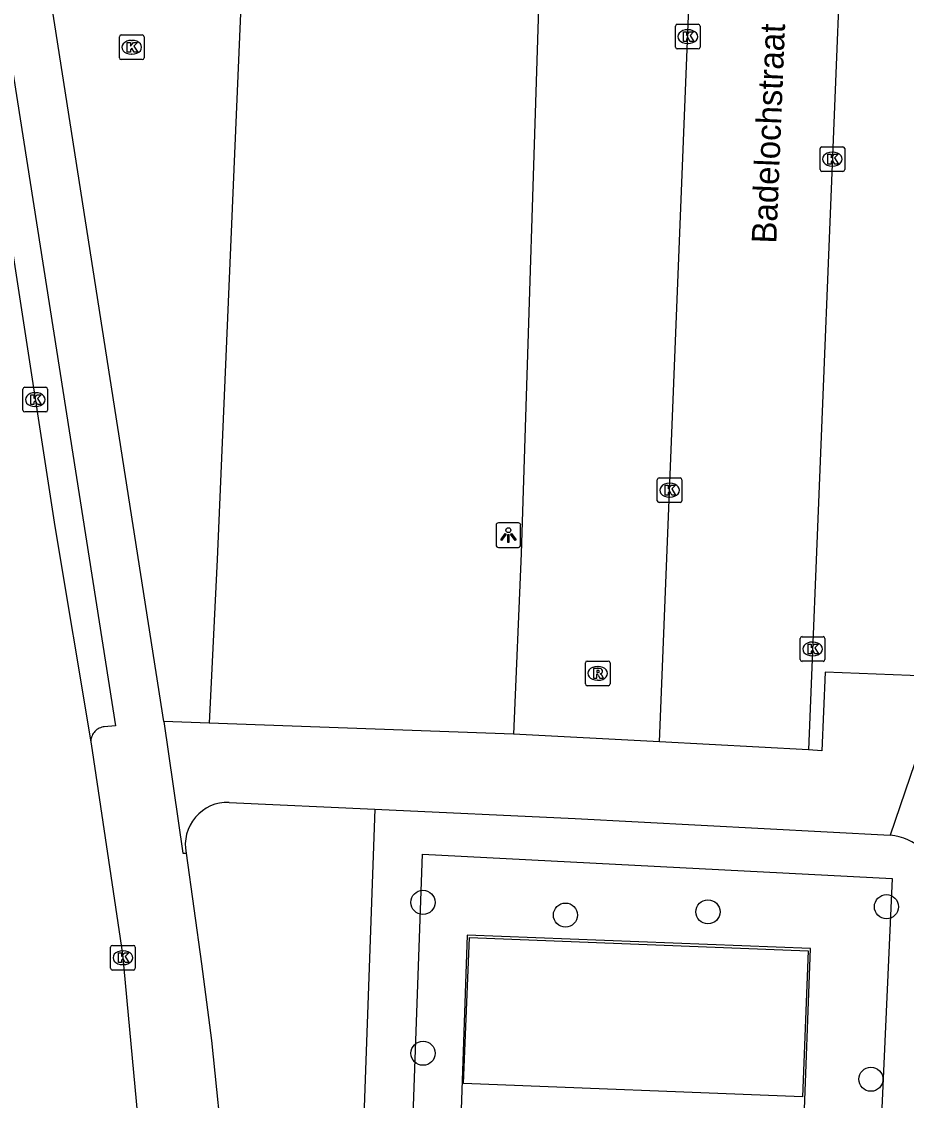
# Model space of a CAD drawing. Extents: x 160077 to 160945, y 386481 to 387498.
# Drawn here: x 160812.49 to 160848.36, y 386677.21 to 386720.98 of the extents above; entities that cross this region are included whole.
import ezdxf

# ---------------------------------------------------------------- set-up
doc = ezdxf.new("R2010")
doc.units = 0
for name, color, linetype in [('IMGEO_Boom', 7, 'Continuous'), ('IMGEO_Groenvoorziening', 7, 'Continuous'), ('IMGEO_Kolk', 7, 'Continuous'), ('IMGEO_Lichtpunt', 7, 'Continuous'), ('IMGEO_Openbare_ruimte_label', 7, 'Continuous'), ('IMGEO_Pand', 7, 'Continuous'), ('IMGEO_Parkeervlak_open', 7, 'Continuous'), ('IMGEO_Rijbaan_lokaal_open', 7, 'Continuous'), ('IMGEO_Rioolput', 7, 'Continuous'), ('IMGEO_Voetpad_open', 7, 'Continuous')]:
    doc.layers.add(name, color=color, linetype=linetype)

msp = doc.modelspace()

# ---------------------------------------------------------------- linework, layer by layer
at = {"layer": 'IMGEO_Boom'}
for centre in [(160828.763, 386685.248), (160840.318, 386684.863), (160847.555, 386685.072), (160834.541, 386684.732), (160828.767, 386679.126), (160846.925, 386678.073)]:
    msp.add_circle(centre, 0.489, dxfattribs=at)
at = {"layer": 'IMGEO_Groenvoorziening'}
for points in [[(160826.808, 386689.026), (160825.569, 386654.256)], [(160840.258, 386655.759), (160827.638, 386656.167), (160828.744, 386687.197), (160847.783, 386686.219), (160846.392, 386655.259), (160843.424, 386655.397)]]:
    msp.add_lwpolyline(points, dxfattribs=at)
at = {"layer": 'IMGEO_Kolk'}
for p, q in [((160839, 386719.942), (160839, 386720.794)), ((160839.075, 386720.868), (160839.927, 386720.868)), ((160840.001, 386720.794), (160840.001, 386719.942)), ((160816.455, 386719.51), (160816.455, 386720.362)), ((160816.53, 386720.436), (160817.382, 386720.436)), ((160817.456, 386720.362), (160817.456, 386719.51)), ((160839.488, 386720.648), (160839.513, 386720.648)), ((160816.943, 386720.216), (160816.968, 386720.216)), ((160839.927, 386719.868), (160839.075, 386719.868)), ((160839.511, 386720.088), (160839.486, 386720.088)), ((160817.382, 386719.436), (160816.53, 386719.436)), ((160816.966, 386719.656), (160816.941, 386719.656)), ((160844.938, 386715.898), (160845.79, 386715.898)), ((160844.863, 386714.972), (160844.863, 386715.824)), ((160845.351, 386715.678), (160845.376, 386715.678)), ((160845.864, 386715.824), (160845.864, 386714.972)), ((160845.374, 386715.118), (160845.349, 386715.118)), ((160845.79, 386714.898), (160844.938, 386714.898)), ((160812.544, 386705.217), (160812.544, 386706.069)), ((160812.619, 386706.143), (160813.471, 386706.143)), ((160813.032, 386705.923), (160813.057, 386705.923)), ((160813.545, 386706.069), (160813.545, 386705.217)), ((160813.471, 386705.143), (160812.619, 386705.143)), ((160813.055, 386705.363), (160813.03, 386705.363)), ((160838.262, 386701.542), (160838.262, 386702.394)), ((160838.337, 386702.468), (160839.189, 386702.468)), ((160839.263, 386702.394), (160839.263, 386701.542)), ((160838.75, 386702.248), (160838.775, 386702.248)), ((160839.189, 386701.468), (160838.337, 386701.468)), ((160838.773, 386701.688), (160838.748, 386701.688)), ((160844.061, 386695.1), (160844.061, 386695.952)), ((160844.136, 386696.026), (160844.988, 386696.026)), ((160844.549, 386695.806), (160844.574, 386695.806)), ((160845.062, 386695.952), (160845.062, 386695.1)), ((160844.988, 386695.026), (160844.136, 386695.026)), ((160844.572, 386695.246), (160844.547, 386695.246)), ((160816.172, 386683.502), (160817.024, 386683.502)), ((160816.097, 386682.576), (160816.097, 386683.428)), ((160816.585, 386683.282), (160816.61, 386683.282)), ((160817.098, 386683.428), (160817.098, 386682.576)), ((160816.608, 386682.722), (160816.583, 386682.722)), ((160817.024, 386682.502), (160816.172, 386682.502))]:
    msp.add_line(p, q, dxfattribs=at)
for points in [[(160839, 386719.942), (160839, 386720.794)], [(160839.075, 386720.868), (160839.927, 386720.868)], [(160840.001, 386720.794), (160840.001, 386719.942)], [(160816.455, 386719.51), (160816.455, 386720.362)], [(160816.53, 386720.436), (160817.382, 386720.436)], [(160817.456, 386720.362), (160817.456, 386719.51)], [(160839.321, 386720.568), (160839.444, 386720.568), (160839.444, 386720.417), (160839.574, 386720.568), (160839.738, 386720.568), (160839.592, 386720.417), (160839.745, 386720.168), (160839.593, 386720.168), (160839.508, 386720.332), (160839.444, 386720.265), (160839.444, 386720.168), (160839.321, 386720.168), (160839.321, 386720.568)], [(160816.776, 386720.136), (160816.899, 386720.136), (160816.899, 386719.985), (160817.029, 386720.136), (160817.193, 386720.136), (160817.047, 386719.985), (160817.2, 386719.736), (160817.048, 386719.736), (160816.963, 386719.9), (160816.899, 386719.833), (160816.899, 386719.736), (160816.776, 386719.736), (160816.776, 386720.136)], [(160839.927, 386719.868), (160839.075, 386719.868)], [(160817.382, 386719.436), (160816.53, 386719.436)], [(160844.938, 386715.898), (160845.79, 386715.898)], [(160844.863, 386714.972), (160844.863, 386715.824)], [(160845.184, 386715.598), (160845.307, 386715.598), (160845.307, 386715.447), (160845.437, 386715.598), (160845.601, 386715.598), (160845.455, 386715.447), (160845.608, 386715.198), (160845.456, 386715.198), (160845.371, 386715.362), (160845.307, 386715.295), (160845.307, 386715.198), (160845.184, 386715.198), (160845.184, 386715.598)], [(160845.864, 386715.824), (160845.864, 386714.972)], [(160845.79, 386714.898), (160844.938, 386714.898)], [(160812.544, 386705.217), (160812.544, 386706.069)], [(160812.619, 386706.143), (160813.471, 386706.143)], [(160812.865, 386705.843), (160812.988, 386705.843), (160812.988, 386705.692), (160813.118, 386705.843), (160813.282, 386705.843), (160813.136, 386705.692), (160813.289, 386705.443), (160813.137, 386705.443), (160813.052, 386705.607), (160812.988, 386705.54), (160812.988, 386705.443), (160812.865, 386705.443), (160812.865, 386705.843)], [(160813.545, 386706.069), (160813.545, 386705.217)], [(160813.471, 386705.143), (160812.619, 386705.143)], [(160838.262, 386701.542), (160838.262, 386702.394)], [(160838.337, 386702.468), (160839.189, 386702.468)], [(160839.263, 386702.394), (160839.263, 386701.542)], [(160838.583, 386702.168), (160838.706, 386702.168), (160838.706, 386702.017), (160838.836, 386702.168), (160839, 386702.168), (160838.854, 386702.017), (160839.007, 386701.768), (160838.855, 386701.768), (160838.77, 386701.932), (160838.706, 386701.865), (160838.706, 386701.768), (160838.583, 386701.768), (160838.583, 386702.168)], [(160839.189, 386701.468), (160838.337, 386701.468)], [(160844.061, 386695.1), (160844.061, 386695.952)], [(160844.136, 386696.026), (160844.988, 386696.026)], [(160845.062, 386695.952), (160845.062, 386695.1)], [(160844.382, 386695.726), (160844.505, 386695.726), (160844.505, 386695.575), (160844.635, 386695.726), (160844.799, 386695.726), (160844.653, 386695.575), (160844.806, 386695.326), (160844.654, 386695.326), (160844.569, 386695.49), (160844.505, 386695.423), (160844.505, 386695.326), (160844.382, 386695.326), (160844.382, 386695.726)], [(160844.988, 386695.026), (160844.136, 386695.026)], [(160816.172, 386683.502), (160817.024, 386683.502)], [(160816.097, 386682.576), (160816.097, 386683.428)], [(160816.418, 386683.202), (160816.541, 386683.202), (160816.541, 386683.051), (160816.671, 386683.202), (160816.835, 386683.202), (160816.689, 386683.051), (160816.842, 386682.802), (160816.69, 386682.802), (160816.605, 386682.966), (160816.541, 386682.899), (160816.541, 386682.802), (160816.418, 386682.802), (160816.418, 386683.202)], [(160817.098, 386683.428), (160817.098, 386682.576)], [(160817.024, 386682.502), (160816.172, 386682.502)]]:
    msp.add_lwpolyline(points, dxfattribs=at)
for centre, start, end in [((160839.077, 386720.792), 91.552, 178.448), ((160839.077, 386720.792), 91.552, 178.448), ((160839.925, 386720.792), 1.552, 88.448), ((160839.925, 386720.792), 1.552, 88.448), ((160816.532, 386720.36), 91.552, 178.448), ((160816.532, 386720.36), 91.552, 178.448), ((160817.38, 386720.36), 1.552, 88.448), ((160817.38, 386720.36), 1.552, 88.448), ((160839.077, 386719.944), 181.552, 268.448), ((160839.077, 386719.944), 181.552, 268.448), ((160839.925, 386719.944), 271.552, 358.448), ((160839.925, 386719.944), 271.552, 358.448), ((160816.532, 386719.512), 181.552, 268.448), ((160816.532, 386719.512), 181.552, 268.448), ((160817.38, 386719.512), 271.552, 358.448), ((160817.38, 386719.512), 271.552, 358.448), ((160844.94, 386715.822), 91.552, 178.448), ((160844.94, 386715.822), 91.552, 178.448), ((160845.788, 386715.822), 1.552, 88.448), ((160845.788, 386715.822), 1.552, 88.448), ((160844.94, 386714.974), 181.552, 268.448), ((160844.94, 386714.974), 181.552, 268.448), ((160845.788, 386714.974), 271.552, 358.448), ((160845.788, 386714.974), 271.552, 358.448), ((160812.621, 386706.067), 91.552, 178.448), ((160812.621, 386706.067), 91.552, 178.448), ((160813.469, 386706.067), 1.552, 88.448), ((160813.469, 386706.067), 1.552, 88.448), ((160812.621, 386705.219), 181.552, 268.448), ((160812.621, 386705.219), 181.552, 268.448), ((160813.469, 386705.219), 271.552, 358.448), ((160813.469, 386705.219), 271.552, 358.448), ((160838.339, 386702.392), 91.552, 178.448), ((160838.339, 386702.392), 91.552, 178.448), ((160839.187, 386702.392), 1.552, 88.448), ((160839.187, 386702.392), 1.552, 88.448), ((160838.339, 386701.544), 181.552, 268.448), ((160838.339, 386701.544), 181.552, 268.448), ((160839.187, 386701.544), 271.552, 358.448), ((160839.187, 386701.544), 271.552, 358.448), ((160844.138, 386695.95), 91.552, 178.448), ((160844.138, 386695.95), 91.552, 178.448), ((160844.986, 386695.95), 1.552, 88.448), ((160844.986, 386695.95), 1.552, 88.448), ((160844.138, 386695.102), 181.552, 268.448), ((160844.138, 386695.102), 181.552, 268.448), ((160844.986, 386695.102), 271.552, 358.448), ((160844.986, 386695.102), 271.552, 358.448), ((160816.174, 386683.426), 91.552, 178.448), ((160816.174, 386683.426), 91.552, 178.448), ((160817.022, 386683.426), 1.552, 88.448), ((160817.022, 386683.426), 1.552, 88.448), ((160816.174, 386682.578), 181.552, 268.448), ((160816.174, 386682.578), 181.552, 268.448), ((160817.022, 386682.578), 271.552, 358.448), ((160817.022, 386682.578), 271.552, 358.448)]:
    msp.add_arc(centre, 0.0765, start, end, dxfattribs=at)
for centre, major_axis, ratio, start_param, end_param in [((160839.487, 386720.368), (-0.387, 0.002), 0.722429, 4.712389, 7.853982), ((160839.512, 386720.368), (-0.39, 0.002), 0.717154, 1.570796, 4.712389), ((160816.942, 386719.936), (-0.387, 0.002), 0.722429, 4.712389, 7.853982), ((160816.967, 386719.936), (-0.39, 0.002), 0.717154, 1.570796, 4.712389), ((160845.35, 386715.398), (-0.387, 0.002), 0.722429, 4.712389, 7.853982), ((160845.375, 386715.398), (-0.39, 0.002), 0.717154, 1.570796, 4.712389), ((160813.031, 386705.643), (-0.387, 0.002), 0.722429, 4.712389, 7.853982), ((160813.056, 386705.643), (-0.39, 0.002), 0.717154, 1.570796, 4.712389), ((160838.749, 386701.968), (-0.387, 0.002), 0.722429, 4.712389, 7.853982), ((160838.774, 386701.968), (-0.39, 0.002), 0.717154, 1.570796, 4.712389), ((160844.548, 386695.526), (-0.387, 0.002), 0.722429, 4.712389, 7.853982), ((160844.573, 386695.526), (-0.39, 0.002), 0.717154, 1.570796, 4.712389), ((160816.584, 386683.002), (-0.387, 0.002), 0.722429, 4.712389, 7.853982), ((160816.609, 386683.002), (-0.39, 0.002), 0.717154, 1.570796, 4.712389)]:
    msp.add_ellipse(centre, major_axis=major_axis, ratio=ratio, start_param=start_param, end_param=end_param, dxfattribs=at)
at = {"layer": 'IMGEO_Lichtpunt'}
for p, q in [((160832.63, 386700.644), (160831.822, 386700.644)), ((160832.63, 386700.644), (160831.822, 386700.644)), ((160831.728, 386700.549), (160831.728, 386699.742)), ((160831.728, 386700.549), (160831.728, 386699.742)), ((160832.724, 386699.742), (160832.724, 386700.549)), ((160832.724, 386699.742), (160832.724, 386700.549)), ((160831.822, 386699.648), (160832.63, 386699.648)), ((160831.822, 386699.648), (160832.63, 386699.648))]:
    msp.add_line(p, q, dxfattribs=at)
for points in [[(160832.102, 386700.213), (160832.141, 386700.185), (160831.953, 386699.923), (160831.915, 386699.95), (160832.102, 386700.213)], [(160832.204, 386700.165), (160832.251, 386700.165), (160832.251, 386699.843), (160832.204, 386699.843), (160832.204, 386700.165)], [(160832.314, 386700.185), (160832.352, 386700.212), (160832.539, 386699.95), (160832.5, 386699.922), (160832.314, 386700.185)]]:
    msp.add_lwpolyline(points, dxfattribs=at)
msp.add_circle((160832.227, 386700.347), 0.0994, dxfattribs=at)
for centre, start, end in [((160831.822, 386700.549), 90, 180), ((160831.822, 386700.549), 90, 180), ((160832.63, 386700.549), 0, 90), ((160832.63, 386700.549), 0, 90), ((160831.822, 386699.742), 180, 270), ((160831.822, 386699.742), 180, 270), ((160832.63, 386699.742), 270, 0), ((160832.63, 386699.742), 270, 360)]:
    msp.add_arc(centre, 0.0946, start, end, dxfattribs=at)
at = {"layer": 'IMGEO_Pand'}
msp.add_lwpolyline([(160830.412, 386677.903), (160830.646, 386683.819), (160844.386, 386683.275), (160844.152, 386677.359), (160830.412, 386677.903)], dxfattribs=at)
at = {"layer": 'IMGEO_Parkeervlak_open'}
for points in [[(160821.538, 386725.444), (160820.414, 386699.16), (160820.1, 386692.52)], [(160833.542, 386724.516), (160832.741, 386699.397), (160832.435, 386692.071)]]:
    msp.add_lwpolyline(points, dxfattribs=at)
at = {"layer": 'IMGEO_Rijbaan_lokaal_open'}
for points in [[(160838.354, 386691.756), (160840.676, 386750), (160842.26, 386789.749)], [(160848.354, 386789.544), (160846.759, 386750), (160844.396, 386691.434)], [(160809.998, 386725.345), (160810.411, 386722.747), (160813.836, 386700.495), (160815.305, 386691.678)], [(160815.305, 386691.678), (160816.579, 386683.142), (160818.438, 386663.211), (160818.431, 386646.739), (160818.24, 386642.214)], [(160844.396, 386691.434), (160838.354, 386691.756)]]:
    msp.add_lwpolyline(points, dxfattribs=at)
at = {"layer": 'IMGEO_Rioolput'}
for p, q in [((160835.347, 386694.112), (160835.347, 386694.964)), ((160835.422, 386695.038), (160836.274, 386695.038)), ((160836.348, 386694.964), (160836.348, 386694.112)), ((160835.835, 386694.818), (160835.86, 386694.818)), ((160836.274, 386694.038), (160835.422, 386694.038)), ((160835.858, 386694.258), (160835.833, 386694.258))]:
    msp.add_line(p, q, dxfattribs=at)
for points in [[(160835.347, 386694.112), (160835.347, 386694.964)], [(160835.422, 386695.038), (160836.274, 386695.038)], [(160836.348, 386694.964), (160836.348, 386694.112)], [(160835.936, 386694.736), (160835.684, 386694.738), (160835.684, 386694.338)], [(160835.684, 386694.338), (160835.808, 386694.338), (160835.808, 386694.5), (160835.819, 386694.5)], [(160835.862, 386694.657), (160835.808, 386694.657), (160835.808, 386694.576)], [(160835.808, 386694.576), (160835.86, 386694.576)], [(160835.866, 386694.471), (160835.937, 386694.338), (160836.077, 386694.338), (160836.012, 386694.464)], [(160836.274, 386694.038), (160835.422, 386694.038)]]:
    msp.add_lwpolyline(points, dxfattribs=at)
for centre, radius, start, end in [((160835.424, 386694.962), 0.0765, 91.552, 178.448), ((160835.424, 386694.962), 0.0765, 91.552, 178.448), ((160836.272, 386694.962), 0.0765, 1.552, 88.448), ((160836.272, 386694.962), 0.0765, 1.552, 88.448), ((160835.818, 386694.447), 0.0533, 26.0293, 88.6989), ((160835.844, 386694.765), 0.19, 274.7715, 282.9687), ((160835.868, 386694.561), 0.0964, 77.0061, 93.1865), ((160835.882, 386694.618), 0.0378, 276.6634, 79.6772), ((160835.935, 386694.626), 0.109, 350.3612, 89.416), ((160835.933, 386694.626), 0.112, 277.5842, 350.9817), ((160835.917, 386694.411), 0.108, 29.5134, 73.7905), ((160835.424, 386694.114), 0.0765, 181.552, 268.448), ((160835.424, 386694.114), 0.0765, 181.552, 268.448), ((160836.272, 386694.114), 0.0765, 271.552, 358.448), ((160836.272, 386694.114), 0.0765, 271.552, 358.448)]:
    msp.add_arc(centre, radius, start, end, dxfattribs=at)
for centre, major_axis, ratio, start_param, end_param in [((160835.834, 386694.538), (-0.387, 0.002), 0.722429, 4.712389, 7.853982), ((160835.859, 386694.538), (-0.39, 0.002), 0.717154, 1.570796, 4.712389)]:
    msp.add_ellipse(centre, major_axis=major_axis, ratio=ratio, start_param=start_param, end_param=end_param, dxfattribs=at)
at = {"layer": 'IMGEO_Voetpad_open'}
for points in [[(160818.263, 386692.587), (160812.902, 386726.822)], [(160809.998, 386725.345), (160811.089, 386725.486), (160816.298, 386692.41), (160815.844, 386692.37), (160815.791, 386692.363), (160815.738, 386692.35), (160815.687, 386692.333), (160815.637, 386692.312), (160815.59, 386692.286), (160815.545, 386692.257), (160815.503, 386692.223), (160815.464, 386692.185), (160815.429, 386692.145), (160815.397, 386692.101), (160815.37, 386692.055), (160815.346, 386692.006), (160815.327, 386691.956), (160815.313, 386691.904), (160815.303, 386691.851), (160815.299, 386691.797), (160815.299, 386691.743), (160815.305, 386691.678)], [(160849.901, 386694.396), (160845.075, 386694.587), (160844.937, 386691.4), (160844.396, 386691.434)], [(160849.901, 386694.396), (160847.701, 386687.968)], [(160820.1, 386692.52), (160818.263, 386692.587)], [(160818.263, 386692.587), (160819.032, 386687.242), (160819.156, 386687.248)], [(160832.435, 386692.071), (160820.1, 386692.52)], [(160838.354, 386691.756), (160832.435, 386692.071)], [(160820.905, 386689.305), (160826.808, 386689.026)], [(160826.808, 386689.026), (160834.938, 386688.648), (160847.701, 386687.968)], [(160819.156, 386687.248), (160819.783, 386682.754), (160820.194, 386679.643), (160820.723, 386674.482)], [(160843.424, 386655.397), (160844.187, 386675.779), (160844.479, 386683.37), (160830.549, 386683.921), (160829.704, 386659.148), (160840.311, 386658.737), (160840.258, 386655.759)]]:
    msp.add_lwpolyline(points, dxfattribs=at)
for centre, radius, start, end in [((160820.851, 386687.579), 1.727, 88.2214, 191.0317), ((160847.584, 386685.918), 2.053, 4.1247, 86.7422)]:
    msp.add_arc(centre, radius, start, end, dxfattribs=at)

# ---------------------------------------------------------------- texts
at = {"layer": 'IMGEO_Openbare_ruimte_label'}
msp.add_text('Badelochstraat', height=1, rotation=87.7071, dxfattribs=at).set_placement((160843.088, 386711.961))

doc.saveas('drawing.dxf')
